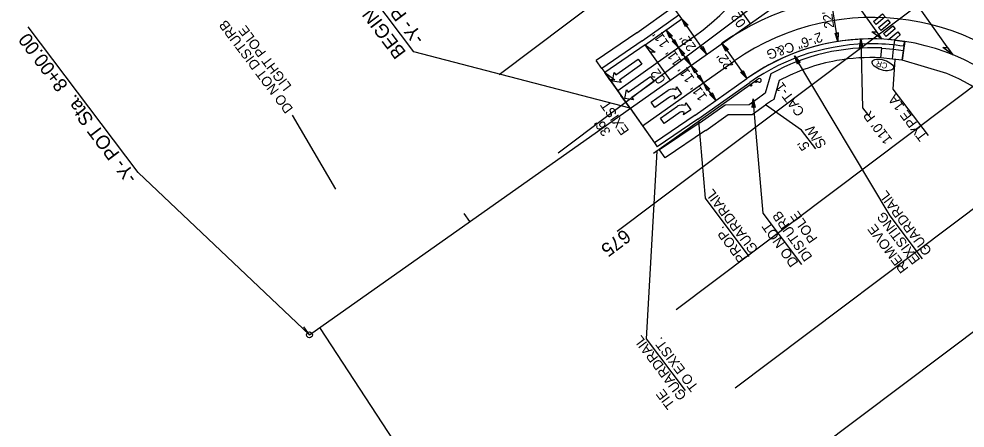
# Model space of a CAD drawing. Extents: x 1262309 to 1264352, y 775189 to 777755.
# Drawn here: x 1262901.3 to 1263383.2, y 776282.7 to 776491.3 of the extents above; entities that cross this region are included whole.
import ezdxf

# ---------------------------------------------------------------- set-up
doc = ezdxf.new("R2010")
doc.units = 0
for name, color, linetype in [('Default', 7, 'Continuous'), ('Old_Level_2', 7, 'Continuous'), ('Prop Conc 2ft 6in Curb and Gutter', 7, 'Continuous'), ('Prop Conc 4in Sidewalk', 7, 'Continuous'), ('Prop Dimension', 7, 'Continuous'), ('Prop Dimension Text', 7, 'Continuous'), ('Prop EOT', 7, 'Continuous'), ('Prop GRAU CAT1 Cell', 7, 'Continuous'), ('Prop Guardrail', 7, 'Continuous'), ('Prop Guardrail Anchor Unit CELL', 7, 'Continuous'), ('Prop Horizontal Alignment', 7, 'Continuous'), ('Prop Horizontal Alignment Station Label', 7, 'Continuous'), ('Prop Horizontal Alignment Tick Label', 7, 'Continuous'), ('Prop Horizontal Alignment Tick Large', 7, 'Continuous'), ('Prop Horizontal Alignment Tick Small', 7, 'Continuous'), ('Prop Lane Arrow CELL', 7, 'Continuous'), ('Prop Lane Lines', 7, 'Continuous'), ('Prop Mkg Solid White Crosswalks', 7, 'Continuous'), ('Prop Paved Shoulder', 7, 'Continuous'), ('Prop Superelevation  Arrow CELL', 7, 'Continuous'), ('Prop Superelevation Label', 7, 'Continuous'), ('Prop Terminator CELL', 7, 'Continuous'), ('Scratch_Level_3', 7, 'Continuous')]:
    doc.layers.add(name, color=color, linetype=linetype)

msp = doc.modelspace()

# ---------------------------------------------------------------- linework, layer by layer
at = {"layer": 'Default'}
msp.add_ellipse((1263341.27, 776467.85), major_axis=(-5.38, 1.6), ratio=0.462467, dxfattribs=at)
at = {"layer": 'Old_Level_2'}
for p, q in [((1263346.8, 776475.84), (1263347.38, 776480.56)), ((1263347.38, 776480.56), (1263352.45, 776479.84)), ((1263352.45, 776479.84), (1263351.77, 776475.28)), ((1263340.28, 776471.54), (1263340.83, 776476.5)), ((1263340.83, 776476.5), (1263346.8, 776475.84)), ((1263346.24, 776470.87), (1263346.8, 776475.84)), ((1263346.8, 776475.84), (1263351.77, 776475.28)), ((1263351.77, 776475.28), (1263351.21, 776470.31)), ((1263346.24, 776470.87), (1263340.28, 776471.54)), ((1263351.21, 776470.31), (1263346.24, 776470.87))]:
    msp.add_line(p, q, dxfattribs=at)
at = {"layer": 'Prop Conc 2ft 6in Curb and Gutter'}
for p, q in [((1263218.79, 776480.21), (1263237.4, 776493.38)), ((1263218.79, 776480.21), (1263198.19, 776466.02)), ((1263351.87, 776477.41), (1263352.45, 776479.84)), ((1263198.19, 776466.02), (1263199.63, 776463.98)), ((1263247.07, 776440.19), (1263273.49, 776458.89)), ((1263247.07, 776440.19), (1263226.4, 776426.16)), ((1263224.95, 776428.2), (1263226.4, 776426.16))]:
    msp.add_line(p, q, dxfattribs=at)
for start, end in [(89.2637, 125.2883), (81.2937, 89.2637)]:
    msp.add_arc((1263335.59, 776371.14), 107.5, start, end, dxfattribs=at)
at = {"layer": 'Prop Conc 4in Sidewalk'}
for p, q in [((1263215.93, 776484.31), (1263234.51, 776497.46)), ((1263215.93, 776484.31), (1263195.3, 776470.11)), ((1263198.19, 776466.02), (1263195.3, 776470.11)), ((1263284.33, 776463.35), (1263281.42, 776453.41)), ((1263288.55, 776459.95), (1263285.7, 776450.22)), ((1263273.16, 776447.63), (1263278.69, 776451.55)), ((1263248.18, 776438.53), (1263260.95, 776447.57)), ((1263260.95, 776447.57), (1263273.16, 776447.63)), ((1263274.76, 776442.64), (1263281.58, 776447.46)), ((1263251.07, 776434.45), (1263262.55, 776442.57)), ((1263262.55, 776442.57), (1263274.76, 776442.64)), ((1263248.23, 776438.56), (1263227.6, 776424.56)), ((1263251.04, 776434.43), (1263230.41, 776420.43)), ((1263230.41, 776420.43), (1263227.52, 776424.51))]:
    msp.add_line(p, q, dxfattribs=at)
for radius, start, end in [(105.5, 87.1879, 119.0715), (100.5, 100.1885, 117.9137), (100.5, 87.3292, 100.1885), (98.5, 123.3653, 125.2883), (93.5, 122.2531, 125.2883)]:
    msp.add_arc((1263335.59, 776371.14), radius, start, end, dxfattribs=at)
at = {"layer": 'Prop Dimension'}
for p, q in [((1263318.43, 776479.93), (1263315.02, 776501.53)), ((1263330.13, 776480.99), (1263331.01, 776446.04)), ((1263346.61, 776455.59), (1263347.57, 776470.72)), ((1263364.54, 776431.9), (1263346.61, 776455.59)), ((1263331.01, 776446.04), (1263334.04, 776442.06))]:
    msp.add_line(p, q, dxfattribs=at)
at = {"layer": 'Prop Dimension Text'}
for p, q in [((1263238.85, 776491.34), (1263208.89, 776533.66)), ((1263251.56, 776473.38), (1263238.85, 776491.34)), ((1263237.8, 776475.9), (1263230.87, 776485.69)), ((1263259.34, 776478.89), (1263272.05, 776460.93)), ((1263243.57, 776467.73), (1263237.8, 776475.9)), ((1263345.02, 776390.85), (1263296.29, 776472.56)), ((1263250.51, 776457.94), (1263243.57, 776467.73)), ((1263256.28, 776449.78), (1263250.51, 776457.94)), ((1263280.3, 776392.33), (1263275.24, 776450.66)), ((1263299.88, 776434.66), (1263281.58, 776447.46)), ((1263040.54, 776442.22), (1263062.62, 776404.47)), ((1263250.9, 776400.01), (1263247.58, 776439.42)), ((1263307.09, 776425.09), (1263299.88, 776434.66)), ((1263220.97, 776328.25), (1263226.38, 776423.84)), ((1263273.14, 776370.18), (1263250.9, 776400.01)), ((1263300.08, 776366.08), (1263280.3, 776392.33)), ((1263361.49, 776368.97), (1263345.02, 776390.85)), ((1263240.84, 776301.87), (1263220.97, 776328.25))]:
    msp.add_line(p, q, dxfattribs=at)
for points in [[(1263240.81, 776487.22), (1263238.85, 776491.34), (1263242.11, 776488.11), (1263241.13, 776488.11)], [(1263232.83, 776481.57), (1263230.87, 776485.69), (1263234.13, 776482.46), (1263233.15, 776482.47)], [(1263235.25, 776480.83), (1263237.22, 776476.71), (1263233.95, 776479.94), (1263234.94, 776479.94)], [(1263239.19, 776472.59), (1263237.22, 776476.71), (1263240.49, 776473.48), (1263239.5, 776473.49)], [(1263241.61, 776471.85), (1263243.57, 776467.73), (1263240.31, 776470.96), (1263241.29, 776470.96)], [(1263241.61, 776471.85), (1263243.57, 776467.73), (1263240.31, 776470.96), (1263241.29, 776470.96)], [(1263241.61, 776471.85), (1263243.57, 776467.73), (1263240.31, 776470.96), (1263241.29, 776470.96)], [(1263245.54, 776463.61), (1263243.57, 776467.73), (1263246.84, 776464.5), (1263245.86, 776464.51)], [(1263247.96, 776462.88), (1263249.93, 776458.75), (1263246.66, 776461.99), (1263247.65, 776461.98)], [(1263251.9, 776454.63), (1263249.93, 776458.75), (1263253.2, 776455.52), (1263252.21, 776455.53)], [(1263254.32, 776453.9), (1263256.28, 776449.78), (1263253.02, 776453.01), (1263254, 776453)], [(1263254.32, 776453.9), (1263256.28, 776449.78), (1263253.02, 776453.01), (1263254, 776453)], [(1263254.32, 776453.9), (1263256.28, 776449.78), (1263253.02, 776453.01), (1263254, 776453)], [(1263274.74, 776446.12), (1263275.24, 776450.66), (1263276.32, 776446.19), (1263275.48, 776446.72)]]:
    msp.add_lwpolyline(points, close=True, dxfattribs=at)
msp.add_circle((1263302.37, 776477.19), 0.0635, dxfattribs=at)
at = {"layer": 'Prop EOT'}
for p, q in [((1263220.22, 776478.16), (1263238.85, 776491.34)), ((1263220.22, 776478.16), (1263199.63, 776463.98)), ((1263199.63, 776463.98), (1263224.95, 776428.2)), ((1263245.64, 776442.24), (1263272.05, 776460.93)), ((1263245.64, 776442.24), (1263224.95, 776428.2))]:
    msp.add_line(p, q, dxfattribs=at)
for centre, radius, start, end in [((1263335.59, 776371.14), 110, 88.6462, 125.2883), ((1263335.59, 776371.14), 110, 81.1849, 125.2883), ((1263335.56, 776371.06), 110.08, 37.0099, 81.1734)]:
    msp.add_arc(centre, radius, start, end, dxfattribs=at)
at = {"layer": 'Prop GRAU CAT1 Cell'}
for p, q in [((1263273.57, 776457.7), (1263276.42, 776459.8)), ((1263273.57, 776457.7), (1263274.13, 776458.11)), ((1263274.13, 776458.11), (1263274.05, 776457.05)), ((1263274.13, 776458.11), (1263274.61, 776457.46)), ((1263276.59, 776459.42), (1263274.82, 776458.62)), ((1263276.07, 776459.54), (1263276.64, 776459.95)), ((1263276.55, 776458.89), (1263276.07, 776459.54)), ((1263276.07, 776459.54), (1263277.11, 776459.3)), ((1263276.42, 776459.8), (1263277.81, 776460.82)), ((1263276.53, 776459.88), (1263276.42, 776459.8)), ((1263276.64, 776459.95), (1263276.55, 776458.89)), ((1263277.11, 776459.3), (1263276.55, 776458.89)), ((1263276.64, 776459.95), (1263277.11, 776459.3)), ((1263278.11, 776459.07), (1263277.05, 776459.39)), ((1263274.05, 776457.05), (1263273.57, 776457.7)), ((1263273.57, 776457.7), (1263274.61, 776457.46)), ((1263274.61, 776457.46), (1263274.05, 776457.05))]:
    msp.add_line(p, q, dxfattribs=at)
msp.add_ellipse((1263278.39, 776460.02), major_axis=(-0.589, 0.8), ratio=0.995379, start_param=2.210226, end_param=6.283185, dxfattribs=at)
at = {"layer": 'Prop Guardrail'}
msp.add_line((1263224.57, 776422.83), (1263273.57, 776457.7), dxfattribs=at)
at = {"layer": 'Prop Horizontal Alignment'}
msp.add_line((1263049.28, 776330.22), (1263743.09, 776821.26), dxfattribs=at)
at = {"layer": 'Prop Horizontal Alignment Station Label'}
for p, q in [((1263102.41, 776474.57), (1263016.02, 776589.26)), ((1262962.04, 776413.01), (1262906.1, 776487.27)), ((1263212.53, 776445.76), (1263102.41, 776474.57)), ((1263049.28, 776330.22), (1262962.04, 776413.01)), ((1263112.94, 776244.9), (1263054.58, 776333.98))]:
    msp.add_line(p, q, dxfattribs=at)
msp.add_circle((1263049.28, 776330.22), 1.5, dxfattribs=at)
at = {"layer": 'Prop Horizontal Alignment Tick Large'}
msp.add_line((1263212.53, 776445.76), (1263207.91, 776452.29), dxfattribs=at)
at = {"layer": 'Prop Horizontal Alignment Tick Small'}
for p, q in [((1263130.9, 776387.99), (1263128.01, 776392.07)), ((1263049.28, 776330.22), (1263046.39, 776334.3))]:
    msp.add_line(p, q, dxfattribs=at)
at = {"layer": 'Prop Lane Arrow CELL'}
for p, q in [((1263205.26, 776462.8), (1263216.69, 776470.89)), ((1263218.59, 776468.19), (1263207.16, 776460.11)), ((1263216.69, 776470.89), (1263218.59, 776468.19)), ((1263203.67, 776459.59), (1263204.39, 776464.02)), ((1263204.39, 776464.02), (1263205.26, 776462.8)), ((1263208.03, 776458.88), (1263203.67, 776459.59)), ((1263207.16, 776460.11), (1263208.03, 776458.88)), ((1263211.53, 776453.94), (1263222.95, 776462.03)), ((1263224.86, 776459.34), (1263213.43, 776451.25)), ((1263222.95, 776462.03), (1263224.86, 776459.34)), ((1263209.94, 776450.74), (1263210.66, 776455.17)), ((1263210.66, 776455.17), (1263211.53, 776453.94)), ((1263223.34, 776448.86), (1263231.95, 776454.95)), ((1263238.81, 776453.13), (1263235.17, 776450.49)), ((1263235.98, 776455.23), (1263236.23, 776456.7)), ((1263236.23, 776456.7), (1263238.81, 776453.13)), ((1263214.3, 776450.03), (1263209.94, 776450.74)), ((1263213.43, 776451.25), (1263214.3, 776450.03)), ((1263225.25, 776446.16), (1263223.34, 776448.86)), ((1263232.71, 776451.45), (1263225.25, 776446.16)), ((1263235.17, 776450.49), (1263235.42, 776451.96)), ((1263240.67, 776447.12), (1263240.92, 776448.59)), ((1263240.92, 776448.59), (1263243.5, 776445.02)), ((1263228.02, 776440.75), (1263236.64, 776446.84)), ((1263243.5, 776445.02), (1263239.85, 776442.38)), ((1263239.85, 776442.38), (1263240.1, 776443.85)), ((1263229.93, 776438.05), (1263228.02, 776440.75)), ((1263237.4, 776443.34), (1263229.93, 776438.05))]:
    msp.add_line(p, q, dxfattribs=at)
for centre, radius, start, end in [((1263234.29, 776450.27), 5.25, 71.3005, 116.6122), ((1263234.61, 776448.8), 3.27, 75.6301, 125.2883), ((1263238.98, 776442.16), 5.25, 71.3005, 116.6122), ((1263239.29, 776440.69), 3.27, 75.6301, 125.2883)]:
    msp.add_arc(centre, radius, start, end, dxfattribs=at)
at = {"layer": 'Prop Lane Lines'}
for p, q in [((1263206.37, 776454.88), (1263245.11, 776482.3)), ((1263218.88, 776436.78), (1263265.69, 776469.91))]:
    msp.add_line(p, q, dxfattribs=at)
for centre, radius, start, end in [((1263181.18, 776573.65), 111.5, 305.0388, 36.738), ((1263335.59, 776371.14), 132, 85.2295, 125.2883), ((1263336.03, 776369.27), 122.79, 37.8117, 124.9498)]:
    msp.add_arc(centre, radius, start, end, dxfattribs=at)
at = {"layer": 'Prop Mkg Solid White Crosswalks'}
for points in [[(1263341.2, 776493.92), (1263342.47, 776492.38), (1263337.85, 776488.55), (1263336.58, 776490.09)], [(1263343.75, 776490.84), (1263345.03, 776489.3), (1263340.41, 776485.47), (1263339.13, 776487.01)], [(1263346.3, 776487.76), (1263347.58, 776486.22), (1263342.96, 776482.39), (1263341.69, 776483.93)], [(1263348.86, 776484.68), (1263350.13, 776483.14), (1263347.01, 776480.55), (1263344.28, 776480.8), (1263344.24, 776480.85)]]:
    msp.add_lwpolyline(points, close=True, dxfattribs=at)
at = {"layer": 'Prop Paved Shoulder'}
for p, q in [((1263351.21, 776470.31), (1263352.45, 776479.84)), ((1263373.93, 776463.5), (1263351.21, 776470.31))]:
    msp.add_line(p, q, dxfattribs=at)
msp.add_arc((1263335.59, 776371.14), 100, 36.9874, 67.456, dxfattribs=at)
at = {"layer": 'Prop Superelevation  Arrow CELL'}
for p, q in [((1263376.97, 776473.07), (1263290.6, 776595.09)), ((1263273.75, 776489.09), (1263258.86, 776510.12)), ((1263324.83, 776503.46), (1263340.71, 776481.03)), ((1263232.93, 776460.2), (1263220.22, 776478.16)), ((1263212.53, 776445.76), (1263199.63, 776463.98)), ((1263212.53, 776445.76), (1263224.95, 776428.2))]:
    msp.add_line(p, q, dxfattribs=at)
for points in [[(1263340.71, 776481.03), (1263335.61, 776484.77), (1263338.04, 776484.8)], [(1263220.22, 776478.16), (1263225.32, 776474.42), (1263222.9, 776474.38)], [(1263376.97, 776473.07), (1263371.87, 776476.81), (1263374.3, 776476.84)], [(1263199.63, 776463.98), (1263204.73, 776460.24), (1263202.3, 776460.21)]]:
    msp.add_lwpolyline(points, close=True, dxfattribs=at)
at = {"layer": 'Prop Terminator CELL'}
for points in [[(1263318.51, 776484.37), (1263318.45, 776479.8), (1263316.95, 776484.14), (1263317.83, 776483.7)], [(1263249.59, 776477.5), (1263251.56, 776473.38), (1263248.29, 776476.61), (1263249.27, 776476.61)], [(1263261.31, 776474.77), (1263259.34, 776478.89), (1263262.61, 776475.66), (1263261.62, 776475.67)], [(1263329.45, 776476.47), (1263330.13, 776480.99), (1263331.02, 776476.48), (1263330.21, 776477.04)], [(1263297.9, 776468.29), (1263296.29, 776472.56), (1263299.27, 776469.06), (1263298.29, 776469.16)], [(1263270.08, 776465.05), (1263272.05, 776460.93), (1263268.78, 776464.16), (1263269.77, 776464.16)]]:
    msp.add_lwpolyline(points, close=True, dxfattribs=at)
at = {"layer": 'Scratch_Level_3'}
for p, q in [((1263145.82, 776463.02), (1263640.93, 776835.94)), ((1263175.91, 776423.09), (1263671.01, 776796)), ((1263205.99, 776383.15), (1263701.09, 776756.06)), ((1263236.07, 776343.21), (1263731.17, 776716.12)), ((1263266.15, 776303.27), (1263761.25, 776676.19)), ((1263296.23, 776263.33), (1263791.33, 776636.25))]:
    msp.add_line(p, q, dxfattribs=at)

# ---------------------------------------------------------------- texts
at = {"layer": 'Default'}
msp.add_text('CR', height=3, rotation=163.4716, dxfattribs=at).set_placement((1263343.95, 776468.6))
at = {"layer": 'Prop Dimension'}
for s, rotation, p in [("22'", 98.2283, (1263316.58, 776486.88)), ('TYPE 1A', 127.0213, (1263364.16, 776431.41)), ("110' R", 127.0213, (1263346.34, 776429.79))]:
    msp.add_text(s, height=5, rotation=rotation, dxfattribs=at).set_placement(p)
at = {"layer": 'Prop Dimension Text'}
for s, rotation, p in [('DO NOT DISTURB', 126.9874, (1263041.17, 776445.55)), ('LIGHT POLE', 126.9874, (1263040.44, 776457.06)), ("11'", 125.2883, (1263232.75, 776478.83)), ("22'", 125.2883, (1263246.5, 776477.03)), ('2\'-6" C&G', 198.8642, (1263309.56, 776484.7)), ("11'", 125.2883, (1263239.38, 776469.53)), ("22'", 125.2883, (1263265.35, 776467.76)), ("11'", 125.2883, (1263245.6, 776460.97)), ("11'", 125.2883, (1263252.07, 776451.64)), ("36'", 124.8705, (1263202.98, 776433.76)), ('S/W', 125.2883, (1263312.83, 776427.41)), ("5'", 125.2883, (1263304.4, 776426.34)), ('GUARDRAIL', 126.9874, (1263278.14, 776373.94)), ('GUARDRAIL', 126.9874, (1263366.54, 776373.08)), ('DISTURB', 125.2883, (1263305.64, 776369.98)), ('POLE', 125.2883, (1263308.23, 776379.31)), ('EXISTING', 126.9874, (1263360.55, 776368.57)), ('DO NOT', 125.2883, (1263298.51, 776367.07)), ('REMOVE', 126.9874, (1263354.56, 776364.06)), ('PROP.', 126.9874, (1263272.15, 776369.43)), ('GUARDRAIL', 126.9874, (1263241.65, 776299.25)), ('TO EXIST.', 126.9874, (1263247.65, 776303.77)), ('TIE', 126.9874, (1263235.66, 776294.74))]:
    msp.add_text(s, height=5, rotation=rotation, dxfattribs=at).set_placement(p)
at = {"layer": 'Prop Guardrail Anchor Unit CELL'}
msp.add_text('CAT-1', height=5, rotation=126.9874, dxfattribs=at).set_placement((1263301.73, 776444.02))
at = {"layer": 'Prop Horizontal Alignment Station Label'}
for s, p in [('BEGIN GRADING AND PAVING', (1263098.77, 776474.33)), ('-Y- POT Sta.  10+00.00', (1263108.28, 776481.49)), ('-Y- POT Sta.  8+00.00', (1262962, 776410.63))]:
    msp.add_text(s, height=7, rotation=126.9874, dxfattribs=at).set_placement(p)
at = {"layer": 'Prop Horizontal Alignment Tick Label'}
msp.add_text('675', height=7, rotation=216.9874, dxfattribs=at).set_placement((1263209.55, 776384.51))
at = {"layer": 'Prop Superelevation Label'}
for s, rotation, p in [('02', 125.2883, (1263271.9, 776489.11)), ('02', 125.2883, (1263230.95, 776460.42)), ('EXIST', 124.8705, (1263212.31, 776434.29))]:
    msp.add_text(s, height=5, rotation=rotation, dxfattribs=at).set_placement(p)

doc.saveas('drawing.dxf')
